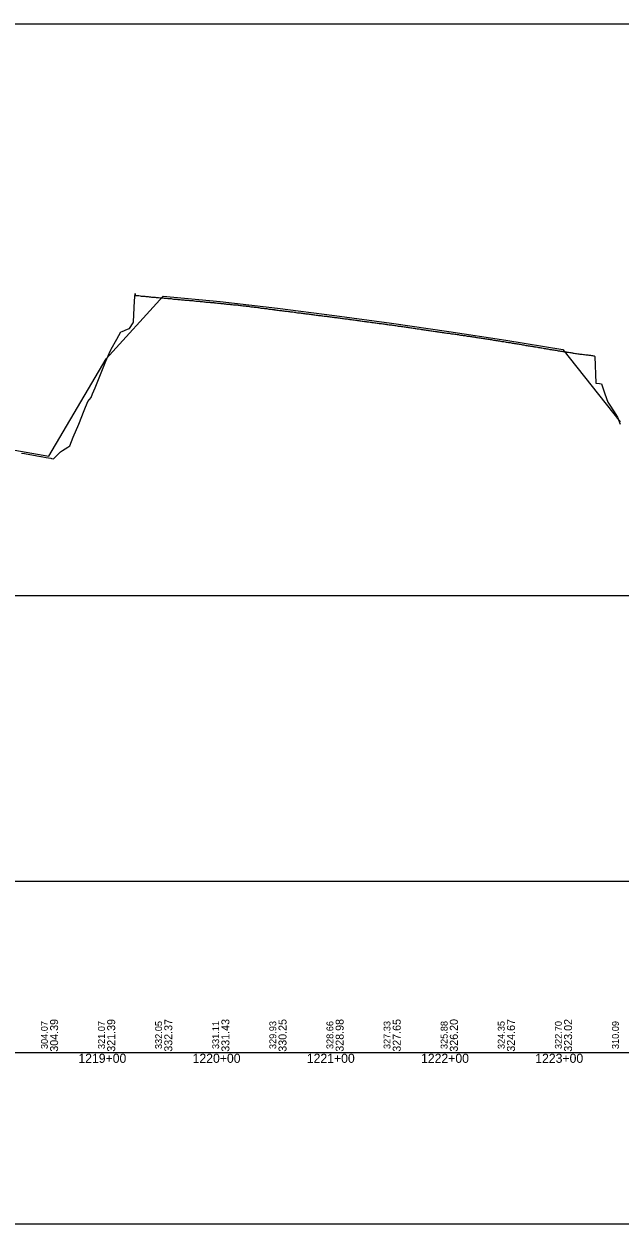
# Model space of a CAD drawing. Extents: x -3627 to 47473, y 2850 to 4350.
# Drawn here: x 9205 to 9727, y 2850 to 3900 of the extents above; entities that cross this region are included whole.
import ezdxf

# ---------------------------------------------------------------- set-up
doc = ezdxf.new("R2010")
doc.units = 0
for name, color, linetype in [('RD_DDB_Profile_EX', 7, 'Continuous'), ('RD_DDB_Profile_PR', 7, 'Continuous'), ('RD_DDB_StaTX', 7, 'Continuous'), ('RD_DDB_StripGrade', 7, 'Continuous'), ('RD_GPK_Profile_Cell', 7, 'Continuous'), ('RD_SHT_ShtClip', 7, 'Continuous')]:
    doc.layers.add(name, color=color, linetype=linetype)

msp = doc.modelspace()

# ---------------------------------------------------------------- linework, layer by layer
at = {"layer": 'RD_DDB_Profile_EX'}
for points in [[(9203.370092, 3524.56259), (9205.938596, 3524.116115), (9207.410687, 3523.86042), (9210.688073, 3523.283845), (9215.437549, 3522.44892), (9216.768155, 3522.21519), (9220.187025, 3521.561165), (9220.597862, 3521.482625), (9224.936502, 3520.749885), (9228.890538, 3520.082515), (9229.685978, 3519.909465), (9231.195274, 3519.58126), (9234.435454, 3522.7338), (9237.530706, 3525.74363), (9239.184931, 3526.79234), (9243.934407, 3529.8005), (9245.493499, 3530.78705), (9248.683883, 3538.47502), (9253.43336, 3549.9226), (9258.182836, 3561.74449), (9261.391216, 3569.72552), (9262.932313, 3571.546055), (9264.244031, 3573.09365), (9265.551776, 3576.439565), (9267.681789, 3581.67911), (9272.431265, 3593.353375), (9277.202087, 3605.07118), (9280.152874, 3611.72795), (9281.506976, 3614.81983), (9281.930218, 3615.58011), (9286.679694, 3624.103735), (9290.260979, 3630.52484), (9291.429171, 3630.9951), (9296.178647, 3632.89987), (9297.738571, 3633.52313), (9300.928123, 3638.431385), (9301.474333, 3639.27116), (9302.379452, 3657.780595), (9302.754326, 3664.181445), (9302.762399, 3662.580115), (9303.325134, 3662.581315), (9304.277082, 3662.43986), (9305.222477, 3662.302585), (9305.6776, 3662.3032), (9306.176696, 3662.303585), (9307.163582, 3662.15947), (9308.164526, 3661.918945), (9309.156315, 3661.87485), (9310.427076, 3661.831705), (9311.161025, 3661.725945), (9312.165233, 3661.4852), (9313.156803, 3661.48192), (9314.157799, 3661.42963), (9315.176552, 3661.28381), (9316.163062, 3661.235995), (9317.1579, 3661.08937), (9318.158957, 3660.98871), (9319.160015, 3660.933835), (9320.297445, 3660.83538), (9321.301842, 3660.73709), (9322.297095, 3660.6419), (9323.312809, 3660.5921), (9324.307987, 3660.495445), (9324.675505, 3660.477935), (9325.311955, 3660.44342), (9326.307088, 3660.39616), (9327.311101, 3660.251595), (9328.315475, 3660.153185), (9329.424981, 3660.09539), (9330.311584, 3660.05033), (9331.306919, 3659.856255), (9332.311039, 3659.85733), (9333.30625, 3659.855895), (9334.310391, 3659.756915), (9335.305807, 3659.42085), (9336.310366, 3659.321285), (9337.305335, 3659.226235), (9338.309894, 3659.17323), (9338.923934, 3659.14148), (9339.301884, 3659.118385), (9340.306542, 3659.023485), (9341.301934, 3658.9227), (9342.306266, 3658.8692), (9343.301768, 3658.721985), (9343.67341, 3658.68496), (9344.306165, 3658.623305), (9345.301657, 3658.52714), (9346.306416, 3658.42653), (9347.301694, 3658.375375), (9348.422887, 3658.3169), (9349.298586, 3658.26849), (9350.30345, 3658.167315), (9351.299167, 3658.069085), (9352.303695, 3657.969755), (9353.299314, 3657.91958), (9354.267937, 3657.7734)], [(9354.267937, 3657.7734), (9354.82659, 3657.668665), (9355.82587, 3657.6209), (9356.825144, 3657.523145), (9357.92184, 3657.464065), (9358.840564, 3657.370525), (9359.839409, 3657.322495), (9360.841403, 3657.22739), (9361.84025, 3657.12936), (9362.839014, 3657.0296), (9363.838261, 3656.931), (9364.837215, 3656.73696), (9365.836168, 3656.736855), (9366.835122, 3656.636785), (9367.420792, 3656.57899), (9367.834123, 3656.537975), (9368.833095, 3656.3902), (9369.832163, 3656.291055), (9370.8315, 3656.240455), (9371.830566, 3656.18991), (9372.170269, 3656.14041), (9372.832866, 3656.043405), (9373.83196, 3655.94091), (9374.831143, 3655.79396), (9375.830326, 3655.74292), (9376.919745, 3655.62838), (9377.829056, 3655.49437), (9378.82827, 3655.444045), (9379.827572, 3655.34244), (9380.826874, 3655.19356), (9381.826195, 3655.093225), (9382.825619, 3654.99104), (9383.825307, 3654.9388), (9384.824643, 3654.837885), (9385.827222, 3654.740125), (9386.418698, 3654.680225), (9386.835921, 3654.63915), (9387.835468, 3654.489185), (9388.835016, 3654.386375), (9389.813418, 3654.335055), (9391.168174, 3654.25603), (9391.989218, 3654.14), (9392.992266, 3653.991265), (9393.986393, 3653.991085), (9394.989446, 3653.796405), (9395.987571, 3653.6017), (9396.990632, 3653.503645), (9397.984748, 3653.30681), (9398.987813, 3653.254995), (9399.982148, 3653.158115), (9400.988999, 3653.0591), (9401.983109, 3652.960505), (9402.986184, 3652.810615), (9403.9805, 3652.66312), (9404.983577, 3652.5621), (9405.416603, 3652.520415), (9405.990457, 3652.4637), (9406.984566, 3652.36455), (9407.987851, 3652.21515), (9408.981959, 3652.11276), (9410.166079, 3651.93687), (9410.982965, 3651.81674), (9411.986253, 3651.71567), (9412.980365, 3651.470165), (9413.983461, 3651.415985), (9414.977575, 3651.31624), (9415.98468, 3651.12068), (9416.978801, 3651.06728), (9417.981906, 3650.96676), (9418.97603, 3650.81542), (9419.983138, 3650.617605), (9420.977273, 3650.51572), (9421.927725, 3650.4153), (9422.925722, 3650.267425), (9423.920065, 3650.11551), (9424.414508, 3650.066815), (9424.926987, 3650.01812), (9425.925006, 3649.773845), (9426.919174, 3649.671505), (9427.926193, 3649.571755), (9429.163985, 3649.43531), (9429.927507, 3649.3213), (9430.925553, 3649.270125), (9431.919745, 3649.119375), (9432.926984, 3649.01907), (9433.921181, 3648.868375), (9434.919165, 3648.767635), (9435.926225, 3648.667955), (9436.925514, 3648.466815), (9437.923561, 3648.3638), (9438.926856, 3648.212535), (9439.924964, 3648.16126), (9440.923162, 3648.012445), (9441.926714, 3647.858495), (9442.924822, 3647.70967), (9443.412414, 3647.63482), (9443.928402, 3647.555525), (9444.926572, 3647.407585), (9445.924842, 3647.30576), (9446.928453, 3647.250065), (9447.250263, 3647.202535)], [(9447.250263, 3647.202535), (9448.252304, 3647.05588), (9449.25423, 3646.907515), (9450.256297, 3646.807745), (9451.254534, 3646.560685), (9452.247791, 3646.460835), (9452.911367, 3646.428785), (9453.249865, 3646.4122), (9454.252056, 3646.31331), (9455.254247, 3646.163195), (9456.2524, 3646.01287), (9457.254591, 3645.915205), (9457.660843, 3645.854775), (9458.247768, 3645.76712), (9459.249763, 3645.618945), (9460.248037, 3645.56581), (9461.250153, 3645.367565), (9462.410319, 3645.236635), (9463.245577, 3645.069455), (9464.24388, 3644.968275), (9465.24612, 3644.917175), (9466.248262, 3644.766015), (9467.250505, 3644.61731), (9468.252453, 3644.46814), (9469.241858, 3644.3177), (9470.244128, 3644.21735), (9471.246296, 3644.118195), (9471.909272, 3644.02532), (9472.313907, 3643.9682), (9473.316088, 3643.86733), (9474.313464, 3643.768825), (9475.315749, 3643.61925), (9476.309032, 3643.468265), (9476.658748, 3643.416725), (9477.3223, 3643.31836), (9478.32459, 3643.21715), (9479.318107, 3643.068305), (9480.320397, 3642.91711), (9481.408225, 3642.75911), (9482.320042, 3642.666615), (9483.313401, 3642.566095), (9484.31576, 3642.41569), (9485.321888, 3642.31647), (9486.315493, 3642.16586), (9487.317921, 3642.01244), (9488.311357, 3641.911455), (9489.317547, 3641.76309), (9490.311228, 3641.612095), (9490.907177, 3641.52162), (9491.313681, 3641.455705), (9492.319938, 3641.30965), (9493.31345, 3641.20823), (9494.542127, 3641.055785), (9495.656654, 3640.93929), (9496.54575, 3640.806215), (9497.543143, 3640.70533), (9498.540793, 3640.555835), (9499.538071, 3640.3591), (9500.544361, 3640.25843), (9501.541801, 3640.011315), (9502.539498, 3639.90994), (9503.536937, 3639.810005), (9504.543266, 3639.65896), (9505.155606, 3639.566915), (9505.540724, 3639.50743), (9506.538474, 3639.359875), (9507.535964, 3639.306625), (9508.542336, 3639.153645), (9509.539825, 3639.00472), (9509.905083, 3638.931345), (9510.537616, 3638.806965), (9511.535159, 3638.754665), (9512.532702, 3638.60534), (9513.539114, 3638.50036), (9514.654559, 3638.34069), (9515.534529, 3638.245115), (9516.532128, 3638.04695), (9517.538877, 3637.941235), (9518.53514, 3637.83998), (9519.532561, 3637.69037), (9520.530332, 3637.538685), (9521.536927, 3637.387575), (9522.534525, 3637.23429), (9523.139136, 3637.13492), (9524.153512, 3637.03024), (9525.142184, 3636.882425), (9526.147583, 3636.735105), (9527.140356, 3636.68486), (9528.141789, 3636.44014), (9529.143558, 3636.38693), (9530.136565, 3636.18962), (9531.138115, 3636.087775), (9532.139971, 3635.88754), (9533.145489, 3635.742985), (9533.652465, 3635.666865), (9534.138122, 3635.59051), (9535.140094, 3635.4898), (9536.142066, 3635.337455), (9537.13488, 3635.23483), (9538.401941, 3635.00907), (9539.138914, 3634.93463)], [(9539.138914, 3634.93463), (9540.144669, 3634.835915), (9541.137479, 3634.637605), (9542.13957, 3634.534755), (9543.151417, 3634.38206), (9544.134591, 3634.229775), (9545.136932, 3634.128105), (9546.139148, 3633.83322), (9547.144704, 3633.782325), (9548.103647, 3633.636965), (9548.609023, 3633.53471), (9549.615061, 3633.384995), (9550.607988, 3633.27887), (9551.610017, 3633.12849), (9552.65037, 3632.92246), (9553.605182, 3632.825115), (9554.611272, 3632.674925), (9555.604596, 3632.525385), (9556.606345, 3632.37096), (9557.608447, 3632.216315), (9558.624255, 3632.115125), (9559.626628, 3631.864075), (9560.629364, 3631.75702), (9561.622823, 3631.60319), (9562.149323, 3631.52271), (9562.583655, 3631.456105), (9563.622641, 3631.35228), (9564.625128, 3631.20088), (9565.627605, 3631.04522), (9566.898799, 3630.852645), (9567.624186, 3630.7413), (9568.630414, 3630.678355), (9569.624152, 3630.339425), (9570.626918, 3630.330905), (9571.648275, 3630.173145), (9572.673655, 3630.071255), (9573.674805, 3629.877825), (9574.672299, 3629.729465), (9575.669793, 3629.62389), (9576.671425, 3629.475455), (9577.669052, 3629.37418), (9578.670519, 3629.13274), (9579.668147, 3629.024295), (9580.66943, 3628.92078), (9581.147228, 3628.872255), (9581.667127, 3628.816785), (9582.668991, 3628.56991), (9583.666755, 3628.46565), (9584.668172, 3628.36644), (9585.896704, 3628.170345), (9586.61455, 3628.02478), (9587.616396, 3627.83008), (9588.055696, 3627.761905), (9588.978035, 3627.66715), (9589.898893, 3627.52962), (9590.818699, 3627.435075), (9591.739373, 3627.297115), (9592.656328, 3627.156635), (9593.57572, 3626.972985), (9594.489246, 3626.87891), (9595.407352, 3626.741325), (9596.316769, 3626.647295), (9597.2325, 3626.5096), (9598.13772, 3626.370385), (9598.651656, 3626.286345), (9599.649583, 3626.130435), (9600.145133, 3626.055905), (9600.651633, 3625.97946), (9601.658347, 3625.827105), (9602.660452, 3625.62588), (9603.600941, 3625.52779), (9604.89461, 3625.34615), (9605.677639, 3625.22205), (9606.674476, 3625.07458), (9607.672036, 3624.92991), (9608.668874, 3624.77973), (9609.678928, 3624.631035), (9610.675895, 3624.38827), (9611.67355, 3624.2403), (9612.670519, 3624.1397), (9613.668162, 3623.9443), (9614.668989, 3623.796435), (9615.666738, 3623.597935), (9616.663835, 3623.399365), (9617.661131, 3623.298515), (9618.667415, 3623.195935), (9619.143039, 3623.101325), (9619.664776, 3622.99725), (9620.666277, 3622.848615), (9621.663697, 3622.70202), (9622.661548, 3622.550635), (9623.892515, 3622.266635), (9624.656723, 3622.15439), (9625.657916, 3622.057635), (9626.655882, 3621.896585), (9627.662012, 3621.65446), (9628.659561, 3621.557205), (9629.611411, 3621.41397), (9630.028666, 3621.31609), (9631.030444, 3621.168805), (9632.028321, 3621.020715)], [(9632.028321, 3621.020715), (9633.030101, 3620.8734), (9633.391468, 3620.800915), (9634.006227, 3620.672925), (9635.008555, 3620.52518), (9636.006215, 3620.32669), (9637.008159, 3620.178985), (9638.140944, 3620.01384), (9638.999697, 3619.87728), (9640.002038, 3619.783215), (9640.999909, 3619.57573), (9642.002051, 3619.23997), (9642.999548, 3619.13467), (9644.001906, 3619.07945), (9644.999593, 3618.829745), (9645.993479, 3618.732395), (9646.995835, 3618.489765), (9647.639897, 3618.39181), (9647.993532, 3618.335725), (9648.995536, 3618.232145), (9649.993439, 3618.032025), (9650.995617, 3617.88034), (9651.993522, 3617.725945), (9652.389373, 3617.627445), (9652.995911, 3617.480465), (9653.993843, 3617.37988), (9654.987192, 3617.22266), (9655.98959, 3616.983475), (9657.13885, 3616.841795), (9657.989737, 3616.67358), (9658.9877, 3616.520225), (9659.990123, 3616.27417), (9660.987474, 3616.16625), (9661.989898, 3615.97024), (9662.992346, 3615.819145), (9663.981695, 3615.661995), (9664.984145, 3615.51323), (9665.982156, 3615.259375), (9667.296478, 3615.15037), (9668.294506, 3615.00547), (9669.292333, 3614.81271), (9670.267036, 3614.622855), (9671.387279, 3614.461965), (9672.267701, 3614.376525), (9673.257455, 3614.13249), (9674.260297, 3613.989695), (9675.258562, 3613.789905), (9676.261231, 3613.646835), (9677.259728, 3613.49669), (9678.262451, 3613.39741), (9679.260942, 3613.202995), (9680.259259, 3613.05102), (9680.886231, 3612.96042), (9681.253432, 3612.907005), (9682.251965, 3612.71004), (9683.254752, 3612.61233), (9684.253279, 3612.41698), (9685.256072, 3612.31929), (9685.635708, 3612.24368), (9686.254193, 3612.118535), (9687.257209, 3611.92526), (9688.255642, 3611.772715), (9689.258517, 3611.62925), (9690.385184, 3611.459545), (9691.246948, 3611.331615), (9692.250018, 3611.18746), (9693.248513, 3611.08458), (9694.251453, 3610.98457), (9695.250085, 3610.83605), (9696.253093, 3610.736965), (9697.251781, 3610.53932), (9698.246133, 3610.440485), (9699.244694, 3610.388595), (9699.884137, 3610.294545), (9700.379988, 3610.292425), (9701.347884, 3610.19506), (9702.317759, 3610.00228), (9703.285239, 3609.856585), (9704.252091, 3609.71098), (9704.633613, 3609.6732), (9705.242658, 3609.13129), (9706.2297, 3585.81436), (9709.38309, 3585.399485), (9711.037899, 3585.1812), (9714.132566, 3576.430415), (9716.75815, 3569.00116), (9718.882042, 3565.67839), (9723.631519, 3558.246095), (9724.990298, 3556.11925), (9727.544092, 3549.90418)]]:
    msp.add_lwpolyline(points, dxfattribs=at)
at = {"layer": 'RD_DDB_Profile_PR'}
msp.add_lwpolyline([(8627.33, 3699.4445), (8677.33, 3698.842), (8727.33, 3697.7065), (8777.33, 3696.4745), (8827.33, 3694.883), (8877.33, 3693.5555), (8927.33, 3691.931), (8977.33, 3617.8285), (9027.33, 3539.2465), (9077.33, 3527.615), (9127.33, 3535.961), (9177.33, 3530.6365), (9227.33, 3521.946), (9277.33, 3606.9595), (9327.33, 3661.8495), (9377.33, 3657.168), (9427.33, 3651.231), (9477.33, 3644.9175), (9527.33, 3638.2385), (9577.33, 3631.0085), (9627.33, 3623.3345), (9677.33, 3615.0895), (9727.33, 3552.025)], dxfattribs=at)
at = {"layer": 'RD_GPK_Profile_Cell'}
msp.add_line((1000, 3000), (46705.077602, 3000), dxfattribs=at)
at = {"layer": 'RD_SHT_ShtClip'}
for points in [[(10000.165, 3400), (10000.165, 3900), (10000.165, 3900), (8500.33, 3900), (8500.33, 3400)], [(8480.33, 3150), (10020, 3150), (10020, 2850), (8480.33, 2850)]]:
    msp.add_lwpolyline(points, close=True, dxfattribs=at)

# ---------------------------------------------------------------- texts
at = {"layer": 'RD_DDB_StaTX'}
for s, p in [('1219+00', (9253.125471, 2991)), ('1220+00', (9353.125471, 2991)), ('1221+00', (9453.125471, 2991)), ('1222+00', (9553.125471, 2991)), ('1223+00', (9653.125471, 2991))]:
    msp.add_text(s, height=8, dxfattribs=at).set_placement(p)
at = {"layer": 'RD_DDB_StripGrade'}
for s, height, p in [('304.07', 6, (9226.33, 3003.073688)), ('304.39', 7, (9235.33, 3000.75)), ('321.07', 6, (9276.33, 3003.073688)), ('321.39', 7, (9285.33, 3000.75)), ('332.05', 6, (9326.33, 3003.073688)), ('332.37', 7, (9335.33, 3000.75)), ('331.11', 6, (9376.33, 3003.073688)), ('331.43', 7, (9385.33, 3000.75)), ('329.93', 6, (9426.33, 3003.073688)), ('330.25', 7, (9435.33, 3000.75)), ('328.66', 6, (9476.33, 3003.073688)), ('328.98', 7, (9485.33, 3000.75)), ('327.33', 6, (9526.33, 3003.073688)), ('327.65', 7, (9535.33, 3000.75)), ('325.88', 6, (9576.33, 3003.073688)), ('326.20', 7, (9585.33, 3000.75)), ('324.35', 6, (9626.33, 3003.073688)), ('324.67', 7, (9635.33, 3000.75)), ('322.70', 6, (9676.33, 3003.073688)), ('323.02', 7, (9685.33, 3000.75)), ('310.09', 6, (9726.33, 3003.073688))]:
    msp.add_text(s, height=height, rotation=90, dxfattribs=at).set_placement(p)

doc.saveas('drawing.dxf')
